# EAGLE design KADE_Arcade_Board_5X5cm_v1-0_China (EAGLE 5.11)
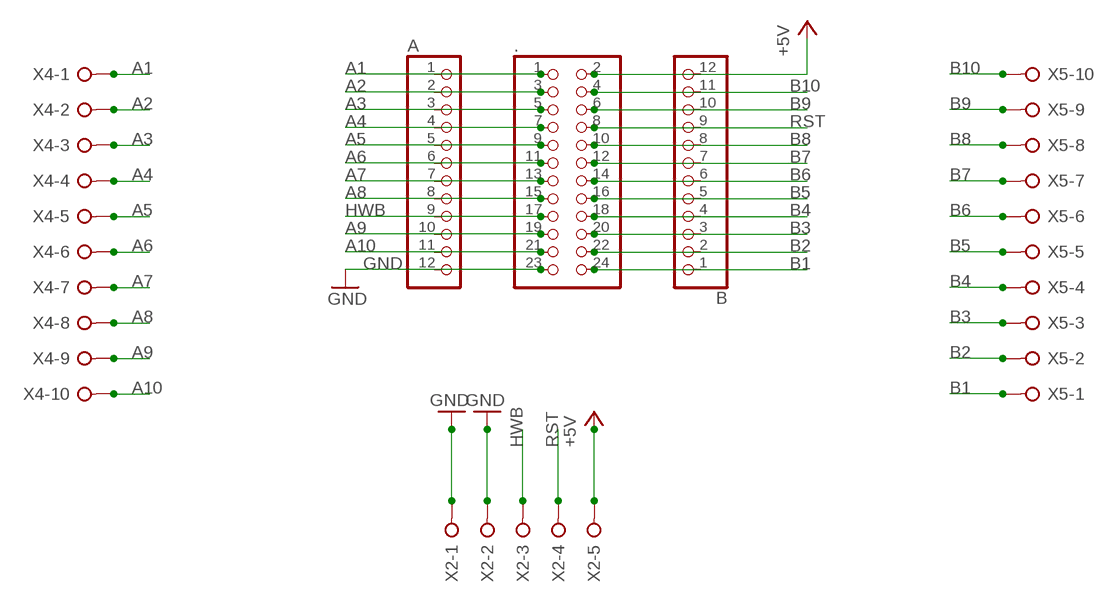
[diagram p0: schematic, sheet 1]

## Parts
.  PINHD-2X12  [2X12]
A  PINHD-1X12  [1X12]
B  PINHD-1X12  [1X12]
X2  W237-05P  [W237-5P]
X4  W237-10P  [W237-10P]
X5  W237-10P  [W237-10P]

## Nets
+5V: ..2 B.12 X2.5
A1: ..1 A.1 X4.1
A2: ..3 A.2 X4.2
A3: ..5 A.3 X4.3
A4: ..7 A.4 X4.4
A5: ..9 A.5 X4.5
A6: ..11 A.6 X4.6
A7: ..13 A.7 X4.7
A8: ..15 A.8 X4.8
A9: ..19 A.10 X4.9
A10: ..21 A.11 X4.10
B1: ..24 B.1 X5.1
B2: ..22 B.2 X5.2
B3: ..20 B.3 X5.3
B4: ..18 B.4 X5.4
B5: ..16 B.5 X5.5
B6: ..14 B.6 X5.6
B7: ..12 B.7 X5.7
B8: ..10 B.8 X5.8
B9: ..6 B.10 X5.9
B10: ..4 B.11 X5.10
GND: ..23 A.12 X2.1 X2.2
HWB: ..17 A.9 X2.3
RST: ..8 B.9 X2.4

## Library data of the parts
. = pinhead:PINHD-2X12: PIN HEADER
A B = pinhead:PINHD-1X12: PIN HEADER
X2 = con-wago-508:W237-05P: WAGO SREW CLAMP; OC_FARNELL: unknown; OC_NEWARK: unknown
X4 X5 = con-wago-508:W237-10P: WAGO SREW CLAMP; OC_FARNELL: unknown; OC_NEWARK: unknown

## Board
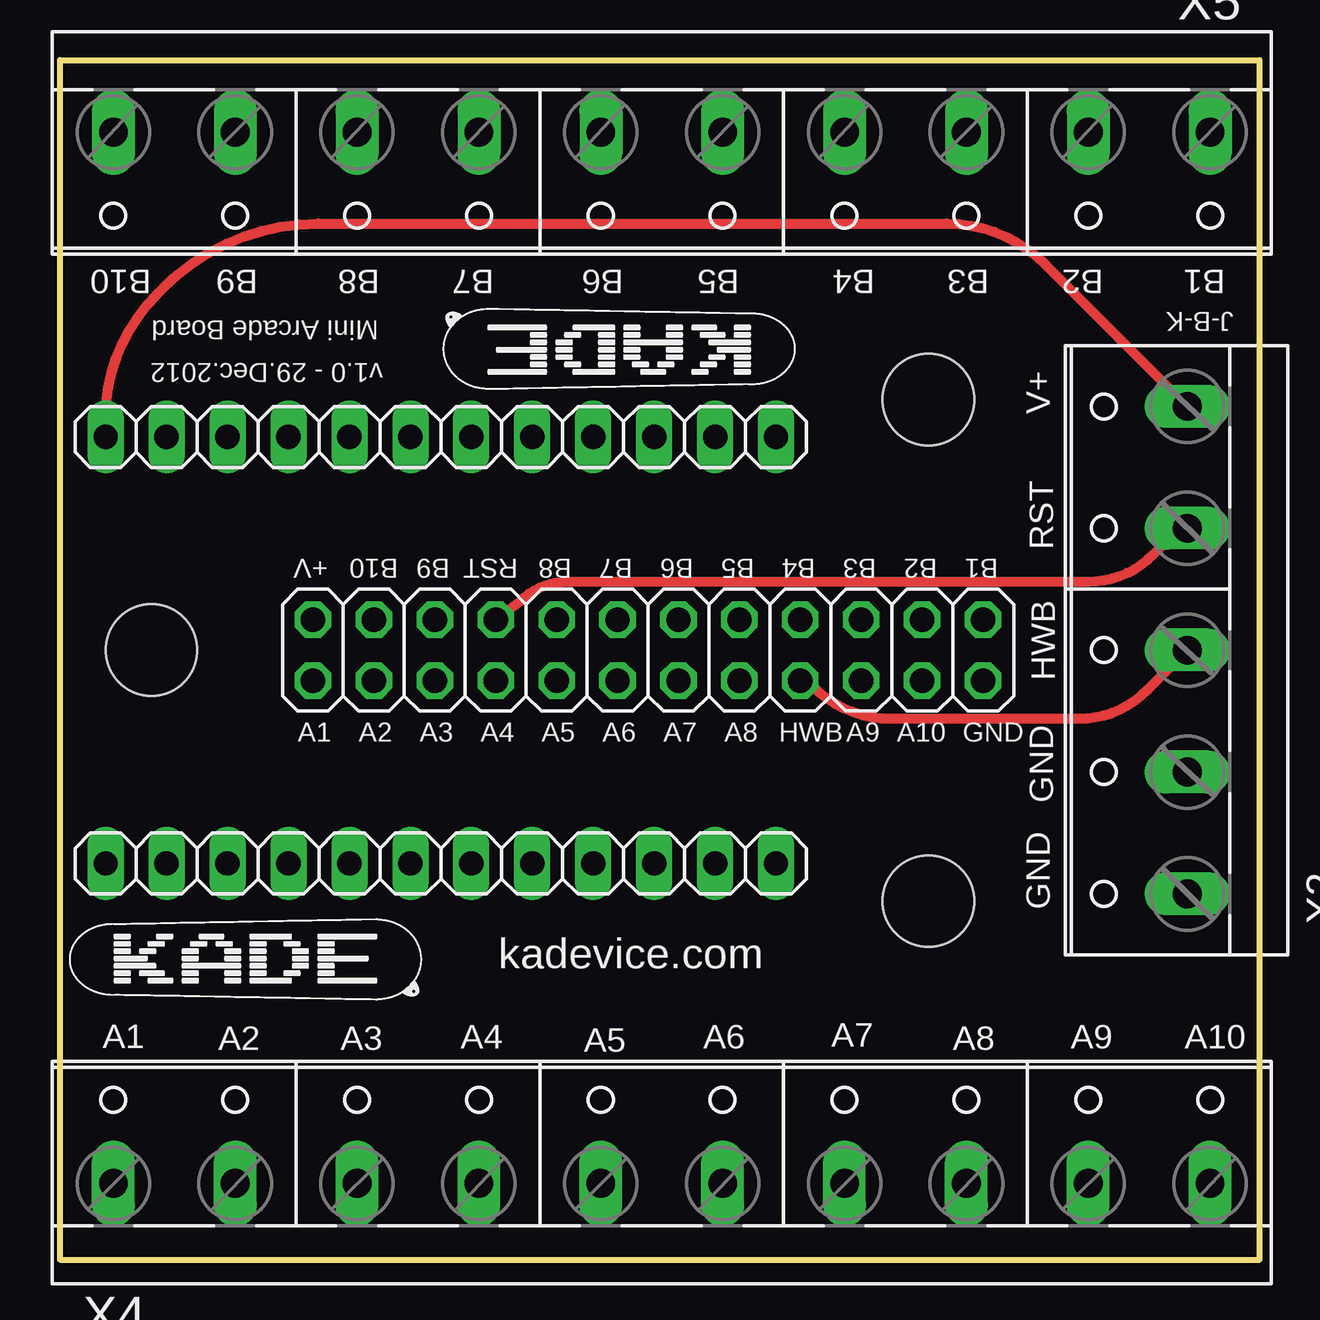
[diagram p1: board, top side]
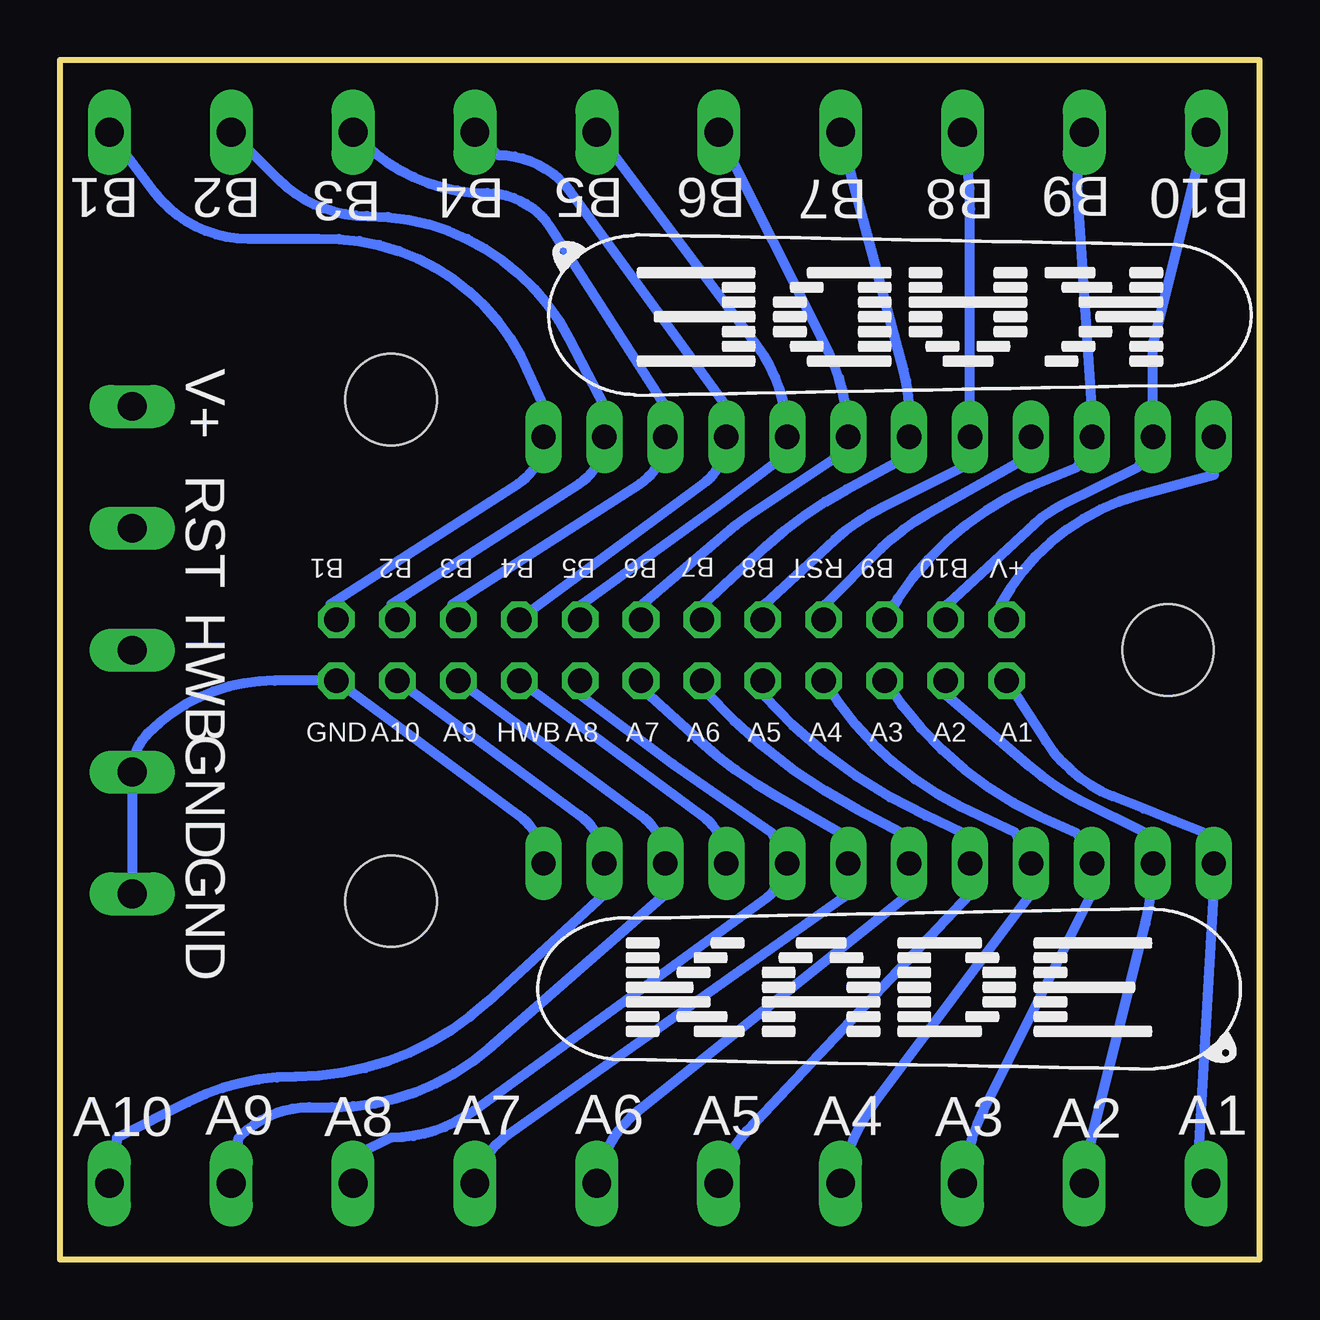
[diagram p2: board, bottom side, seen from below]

Size 50 x 50 mm. Coordinates in mm from the lower left corner, seen from the top.
Outline: 0,0 50,0 50,50 0,50 0,0
Copper layers (1*16): Top 0.035mm / dielectric 1.5mm / Bottom 0.035mm
Design rules "Fusion_eagle_rule_v1.1": minimum track width 6mil, minimum drill 12mil, track to track 6mil, track to pad 6mil, pad to pad 6mil, via to via 6mil, smd to smd 0mil, copper to edge 10mil, drill to drill 10mil, minimum pad ring 10mil, minimum via ring 6mil, stop-mask expansion 2mil, vias tented up to drill 100mil, thermal gap 10mil
Holes 3.81 mm at 3.81,25.4 36.2,35.84 36.2,14.94

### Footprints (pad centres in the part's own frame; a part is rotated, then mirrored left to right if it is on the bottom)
2X12 = drill 1.016 octagon: 1 -13.97,-1.27; 2 -13.97,1.27; 3 -11.43,-1.27; 4 -11.43,1.27; 5 -8.89,-1.27; 6 -8.89,1.27; 7 -6.35,-1.27; 8 -6.35,1.27; 9 -3.81,-1.27; 10 -3.81,1.27; 11 -1.27,-1.27; 12 -1.27,1.27; 13 1.27,-1.27; 14 1.27,1.27; 15 3.81,-1.27; 16 3.81,1.27; 17 6.35,-1.27; 18 6.35,1.27; 19 8.89,-1.27; 20 8.89,1.27; 21 11.43,-1.27; 22 11.43,1.27; 23 13.97,-1.27; 24 13.97,1.27
1X12 = drill 1.016 long: 1 -13.97,0; 2 -11.43,0; 3 -8.89,0; 4 -6.35,0; 5 -3.81,0; 6 -1.27,0; 7 1.27,0; 8 3.81,0; 9 6.35,0; 10 8.89,0; 11 11.43,0; 12 13.97,0
W237-5P = drill 1.194 long: 1 -10.16,-0.635; 2 -5.08,-0.635; 3 0,-0.635; 4 5.08,-0.635; 5 10.16,-0.635
W237-10P = drill 1.194 long: 1 -22.86,-0.635; 2 -17.78,-0.635; 3 -12.7,-0.635; 4 -7.62,-0.635; 5 -2.54,-0.635; 6 2.54,-0.635; 7 7.62,-0.635; 8 12.7,-0.635; 9 17.78,-0.635; 10 22.86,-0.635

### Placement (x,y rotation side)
.  24.51,25.4 0 top
A  15.88,16.51 0 top
B  15.88,34.29 180 top
X2  46.35,25.4 90 top
X4  25.08,3.81 0 top
X5  25.08,46.35 180 top

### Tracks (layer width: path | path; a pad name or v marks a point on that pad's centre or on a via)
+5V
  Top 0.406: B.12 1.91,35.06 arc-45 4.05,40.25 4.32,40.52 arc-45 10.75,43.18 36.95,43.18 arc-45 41.08,41.47 X2.5
  Bottom 0.406: B.12 1.91,32.7 5.05,31.84 arc-46 10.79,27.3 ..2
A1
  Bottom 0.406: X4.1 2.54,4.45 1.91,15.24 A.1 arc-103 2.29,17.78 arc0 6.1,19.3 arc35 8.89,21.59 ..1
A2
  Bottom 0.406: X4.2 6.99,5.08 4.75,14.01 arc-14 A.2 4.76,17.78 7.41,19.1 arc14 9.56,20.53 13.02,23.5 ..3
A3
  Bottom 0.406: X4.3 12.27,3.85 arc17 11.51,6.19 6.99,15.24 A.3 7.62,17.78 9.15,18.46 arc32 ..5
A4
  Bottom 0.406: X4.4 17.46,3.19 arc27 16,6.61 9.53,15.24 A.4 10.16,17.78 12.45,18.86 arc32 ..7
A5
  Bottom 0.406: X4.5 arc29 21.33,5.4 12.06,15.24 A.5 12.38,17.78 13.91,18.5 arc23 20.64,23.5 ..9
A6
  Bottom 0.406: X4.6 27.61,3.28 arc42 25.88,6.22 14.61,15.24 A.6 14.92,17.78 16.74,18.74 arc20 23.04,23.63 ..11
A7
  Bottom 0.406: X4.7 arc41 31.32,5.2 17.14,15.24 A.7 17.46,17.78 20.08,19.27 arc13 23.46,21.74 25.4,23.5 ..13
A8
  Bottom 0.406: X4.8 37.47,4.45 36.2,5.08 arc-36 32.75,6.2 20.52,15.1 arc-27 20.21,15.46 A.8 20.32,17.78 24.45,20.64 28.26,23.5 ..15
A9
  Bottom 0.406: ..19 25.8,18.52 arc54 A.10 24.77,15.24 32.11,8.81 arc41 38.66,6.35 39.61,6.35 arc-45 42.45,5.17 42.55,5.08 X4.9
A10
  Bottom 0.406: X4.10 47.62,5.08 44.65,6.57 arc27 40.2,7.62 arc-43 32.15,10.77 27.3,15.24 A.11 arc-54 28.34,18.52 ..21
B1
  Bottom 0.406: ..24 38.73,27.3 30.91,32.33 arc-57 B.1 29.84,35.56 30.45,36.88 arc-70 39.24,42.55 42.14,42.55 arc53 46.09,44.52 X5.1
B2
  Bottom 0.406: ..22 36.2,27.3 28.37,32.33 arc-57 B.2 27.3,35.56 28.77,38.38 arc-63 37.2,43.5 arc45 40.9,45.03 X5.2
B3
  Bottom 0.406: ..20 33.66,27.3 25.83,32.33 arc-57 B.3 24.77,35.56 29.56,43.02 arc-57 32.19,44.45 arc49 X5.3
B4
  Bottom 0.406: ..18 23.26,32.28 arc-54 B.4 22.23,35.56 28.72,44.5 arc-54 31.75,46.04 X5.4
B5
  Bottom 0.406: X5.5 20.95,38.1 arc37 B.5 20,33.34 22.54,31.43 28.26,27.3 ..16
B6
  Bottom 0.406: X5.6 18,37.9 arc27 B.6 17.78,33.34 21.35,30.96 arc-7 21.81,30.61 25.72,27.3 ..14
B7
  Bottom 0.406: X5.7 17.16,45.79 arc-1 17.13,45.65 14.84,37.09 arc15 14.61,35.27 B.7 14.92,33.34 17.22,32.1 arc-14 20.57,29.71 23.18,27.3 ..12
B8
  Bottom 0.406: X5.8 12.28,46.37 arc9 12.06,43.79 B.8 12.38,33.02 15.72,31.35 arc-16 17.74,29.96 20.64,27.3 ..10
B9
  Bottom 0.406: X5.9 7.51,45.75 arc-13 7.58,44.41 6.99,35.56 B.10 7.62,33.02 9.59,32.19 arc-37 ..6
B10
  Bottom 0.406: X5.10 4.45,38.1 B.11 5.08,33.02 8.29,31.42 arc-16 9.39,30.66 13.02,27.3 ..4
GND
  Bottom 0.406: A.12 arc-54 30.88,18.52 ..23 41.04,24.13 arc-45 46.32,21.95 arc-45 X2.2 X2.1
HWB
  Top 0.406: ..17 31.32,23.93 arc45 34.66,22.54 42.45,22.54 arc45 45.32,23.73 X2.3
  Bottom 0.406: A.9 arc-54 23.26,18.52 ..17
RST
  Top 0.406: ..8 19.17,27.43 arc-45 21.18,28.26 42.87,28.26 arc45 45.57,29.38 46.67,30.48 X2.4
  Bottom 0.406: ..8 18.1,27.3 15.77,29.63 arc16 13.87,31.07 9.84,33.34 B.9

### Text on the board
tPlace: B10 | B9 | B8 | B7 | B6 | B5 | B4 | B3 | B2 | B1 | Mini Arcade Board | J-B-K | v1.0 - 29.Dec.2012 | V+ | RST | +V | B10 | B9 | RST | B8 | B7 | B6 | B5 | B4 | B3 | B2 | B1 | HWB | A1 | A2 | A3 | A4 | A5 | A6 | A7 | A8 | HWB | A9 | A10 | GND | GND | GND | kadevice.com | A1 | A2 | A3 | A4 | A5 | A6 | A7 | A8 | A9 | A10
bPlace: B10 | B9 | B8 | B7 | B6 | B5 | B4 | B3 | B2 | B1 | V+ | RST | +V | B10 | B9 | RST | B8 | B7 | B6 | B5 | B4 | B3 | B2 | B1 | HWB | A1 | A2 | A3 | A4 | A5 | A6 | A7 | A8 | HWB | A9 | A10 | GND | GND | GND | A1 | A2 | A3 | A4 | A5 | A6 | A7 | A8 | A9 | A10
